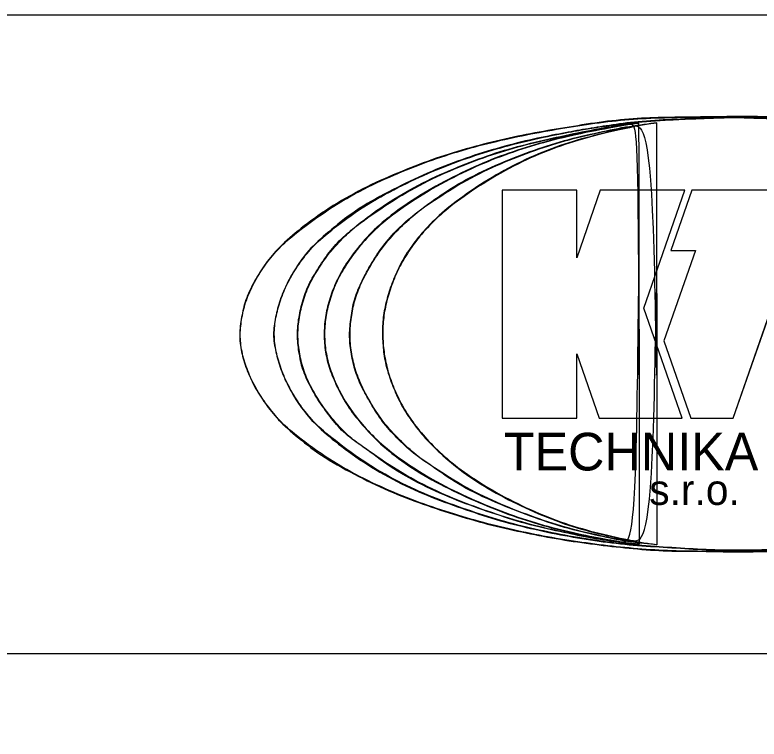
# Model space of a CAD drawing. Extents: x 25 to 46, y -90 to -60.3.
# Drawn here: x 37.705 to 40.036, y -77.068 to -74.8 of the extents above; entities that cross this region are included whole.
import ezdxf

# ---------------------------------------------------------------- set-up
doc = ezdxf.new("R2010")
doc.units = 0
doc.layers.add('_popis', color=7, linetype='Continuous')
doc.layers.add('Rozpiska_pole_6', color=7, linetype='Continuous')

msp = doc.modelspace()

# ---------------------------------------------------------------- linework, layer by layer
at = {"layer": '_popis'}
for p, q in [((39.2313, -75.3488), (39.2313, -76.0628)), ((39.465, -75.3488), (39.2313, -75.3488)), ((39.5386, -75.3488), (39.465, -75.5605)), ((39.465, -75.5605), (39.465, -75.3488)), ((39.8036, -75.3488), (39.5386, -75.3488)), ((39.675, -75.7182), (39.8036, -75.3488)), ((39.825, -75.3488), (39.7594, -75.5375)), ((40.2641, -75.3488), (39.825, -75.3488)), ((39.8369, -75.5375), (39.7381, -75.8213)), ((39.7594, -75.5375), (39.8369, -75.5375)), ((39.9551, -76.0628), (40.1379, -75.5375)), ((39.795, -76.0628), (39.675, -75.7182)), ((39.7381, -75.8213), (39.8222, -76.0628)), ((39.465, -76.0628), (39.465, -75.8616)), ((39.465, -75.8616), (39.535, -76.0628)), ((39.2313, -76.0628), (39.465, -76.0628)), ((39.535, -76.0628), (39.795, -76.0628)), ((39.8222, -76.0628), (39.9551, -76.0628))]:
    msp.add_line(p, q, dxfattribs=at)
for points in [[(39.2313, -75.3488), (39.2313, -76.0628), (39.465, -76.0628), (39.465, -75.8616), (39.535, -76.0628), (39.795, -76.0628), (39.675, -75.7182), (39.8036, -75.3488), (39.5386, -75.3488), (39.465, -75.5605), (39.465, -75.3488), (39.2313, -75.3488)], [(39.825, -75.3488), (39.7594, -75.5375), (39.8369, -75.5375), (39.7381, -75.8213), (39.8222, -76.0628), (39.9551, -76.0628), (40.1379, -75.5375), (40.1984, -75.5375), (40.2641, -75.3488), (39.825, -75.3488)]]:
    msp.add_lwpolyline(points, dxfattribs=at)
for points in [[(39.9639, -75.1182), (39.9235, -75.1188), (39.852, -75.1199), (39.7448, -75.1208), (39.642, -75.1242), (39.5347, -75.1357), (39.4277, -75.1537), (39.3201, -75.1713), (39.2128, -75.1946), (39.1051, -75.2223), (38.9975, -75.2573), (38.8906, -75.3005), (38.7817, -75.3493), (38.6736, -75.4136), (38.589, -75.4768), (38.5246, -75.5353), (38.4849, -75.5846), (38.452, -75.639), (38.4265, -75.6924), (38.4148, -75.7474), (38.4067, -75.8011), (38.4133, -75.8559), (38.4303, -75.9096), (38.4542, -75.9643), (38.4893, -76.0177), (38.5268, -76.0666), (38.5904, -76.1238), (38.6724, -76.1873), (38.7823, -76.2472), (38.8896, -76.2978), (38.9979, -76.3377), (39.1054, -76.3729), (39.2125, -76.4023), (39.3197, -76.4256), (39.427, -76.4454), (39.5348, -76.4603), (39.6419, -76.4721), (39.7493, -76.4805), (39.8565, -76.4792), (39.9639, -76.483), (40.0712, -76.4798), (40.1532, -76.4786), (40.1993, -76.4763), (40.2097, -76.4757)], [(39.9639, -75.1182), (39.8427, -75.1199), (39.7495, -75.1211), (39.6423, -75.1255), (39.5351, -75.1368), (39.4279, -75.1536), (39.3205, -75.1722), (39.2133, -75.1952), (39.1061, -75.2232), (38.9987, -75.2583), (38.8915, -75.3009), (38.7849, -75.3503), (38.6775, -75.4138), (38.5703, -75.4945), (38.5286, -75.5334), (38.4849, -75.5873), (38.4523, -75.6406), (38.4282, -75.6944), (38.4153, -75.7478), (38.4091, -75.8015), (38.4147, -75.8543), (38.431, -75.9085), (38.4551, -75.9623), (38.4888, -76.0156), (38.532, -76.0694), (38.5702, -76.1052), (38.6774, -76.1865), (38.7846, -76.2471), (38.8906, -76.2964), (38.9989, -76.3373), (39.1065, -76.3723), (39.2131, -76.4014), (39.3197, -76.425), (39.4275, -76.4446), (39.535, -76.4598), (39.6427, -76.4716), (39.7487, -76.4789), (39.8568, -76.4801), (39.9639, -76.4818), (40.0711, -76.4801), (40.1786, -76.4773), (40.2858, -76.4705), (40.3924, -76.4605), (40.4999, -76.4442), (40.6071, -76.4251), (40.7143, -76.401), (40.8218, -76.3713), (40.929, -76.336), (41.0362, -76.2945), (41.1428, -76.2446), (41.2508, -76.1813), (41.3585, -76.0978), (41.3905, -76.0692), (41.4326, -76.0159), (41.468, -75.9626), (41.4928, -75.9085), (41.5102, -75.8552), (41.5187, -75.8015), (41.5124, -75.748), (41.4939, -75.6942), (41.4698, -75.6394), (41.4378, -75.5872), (41.3924, -75.5334), (41.3593, -75.5009), (41.2509, -75.417), (41.1437, -75.3537), (41.0373, -75.3029), (40.9295, -75.2614), (40.8218, -75.2244), (40.7152, -75.1964), (40.6071, -75.1722), (40.4994, -75.1537), (40.3917, -75.1386), (40.2853, -75.125), (40.1784, -75.1211), (40.0713, -75.1192), (39.9639, -75.1182), (39.9639, -75.1182), (39.9639, -75.1182)], [(39.9639, -75.1211), (39.9997, -75.1226), (40.0713, -75.1255), (40.1787, -75.1265), (40.2858, -75.1383), (40.393, -75.1519), (40.5005, -75.1698), (40.6076, -75.1935), (40.7158, -75.2191), (40.8227, -75.2556), (40.9309, -75.2969), (41.0378, -75.3497), (41.1493, -75.4096), (41.2316, -75.4752), (41.2925, -75.5363), (41.331, -75.5848), (41.364, -75.639), (41.3885, -75.6928), (41.4013, -75.7476), (41.406, -75.8017), (41.4019, -75.8563), (41.3856, -75.9101), (41.3615, -75.9642), (41.3273, -76.0178), (41.2909, -76.0655), (41.2291, -76.1234), (41.1493, -76.1893), (41.0386, -76.2517), (40.9304, -76.3018), (40.8228, -76.3436), (40.715, -76.3773), (40.6078, -76.4072), (40.5001, -76.4295), (40.393, -76.4491), (40.2855, -76.4596), (40.1784, -76.4688), (40.0713, -76.4757), (39.9639, -76.4792), (39.8566, -76.4751), (39.7494, -76.4675), (39.6419, -76.4616), (39.5346, -76.4489), (39.4272, -76.4315), (39.3199, -76.4087), (39.2119, -76.3821), (39.1053, -76.3453), (38.9969, -76.3064), (38.8884, -76.2571), (38.7805, -76.1918), (38.696, -76.1276), (38.6313, -76.0686), (38.5928, -76.0182), (38.5608, -75.9637), (38.5367, -75.9099), (38.5218, -75.8558), (38.5123, -75.8015), (38.5206, -75.7471), (38.5345, -75.693), (38.5572, -75.6389), (38.589, -75.5849), (38.6276, -75.5322), (38.6946, -75.4726), (38.7792, -75.4054), (38.8901, -75.3461), (38.997, -75.2943), (39.1048, -75.2523), (39.2124, -75.218), (39.32, -75.1904), (39.4116, -75.1723), (39.4832, -75.1591), (39.5546, -75.1477), (39.6419, -75.1348), (39.7494, -75.1281), (39.8567, -75.1236), (39.9282, -75.122), (39.9639, -75.1211)], [(39.9639, -75.1211), (39.8567, -75.124), (39.7495, -75.1284), (39.6423, -75.1363), (39.5351, -75.1509), (39.4869, -75.1587), (39.428, -75.1694), (39.3205, -75.1913), (39.2133, -75.2188), (39.1059, -75.2532), (38.9988, -75.2952), (38.8914, -75.3463), (38.7848, -75.4063), (38.6775, -75.4883), (38.6298, -75.5333), (38.5888, -75.5872), (38.558, -75.6404), (38.5355, -75.6944), (38.5215, -75.7477), (38.5153, -75.8015), (38.5226, -75.8551), (38.5377, -75.9083), (38.5613, -75.9622), (38.5928, -76.0158), (38.6349, -76.0696), (38.6775, -76.11), (38.7847, -76.1919), (38.8914, -76.256), (38.9986, -76.3054), (39.1058, -76.3452), (39.2132, -76.3807), (39.3204, -76.4082), (39.4276, -76.4306), (39.535, -76.4482), (39.6422, -76.4605), (39.7494, -76.4678), (39.8567, -76.4745), (39.9639, -76.4779), (40.0711, -76.4751), (40.1786, -76.4684), (40.2852, -76.4594), (40.3924, -76.4476), (40.4999, -76.4291), (40.607, -76.4061), (40.7142, -76.3769), (40.8217, -76.3426), (40.9289, -76.3011), (41.0361, -76.2512), (41.1435, -76.1886), (41.2507, -76.1028), (41.285, -76.0695), (41.3277, -76.0156), (41.3608, -75.9624), (41.3849, -75.9085), (41.4, -75.8553), (41.4045, -75.802), (41.4, -75.7479), (41.3871, -75.6947), (41.3636, -75.6408), (41.331, -75.5872), (41.2883, -75.5333), (41.2507, -75.4952), (41.1436, -75.4105), (41.0362, -75.3496), (40.929, -75.298), (40.8218, -75.256), (40.7144, -75.2206), (40.6073, -75.1937), (40.5001, -75.1707), (40.3926, -75.1526), (40.2855, -75.1385), (40.1786, -75.1283), (40.0714, -75.1249), (39.9639, -75.1211), (39.9639, -75.1211), (39.9639, -75.1211)], [(40.2097, -76.4757), (40.235, -76.4743), (40.296, -76.4699), (40.3931, -76.4618), (40.5, -76.4443), (40.6076, -76.426), (40.715, -76.4017), (40.8225, -76.3721), (40.93, -76.3366), (41.0376, -76.2954), (41.1457, -76.2449), (41.256, -76.1823), (41.3346, -76.1179), (41.398, -76.0648), (41.4318, -76.0169), (41.4691, -75.965), (41.4932, -75.9098), (41.5113, -75.8562), (41.5216, -75.8018), (41.5143, -75.7463), (41.4938, -75.6932), (41.471, -75.6383), (41.4374, -75.5837), (41.3984, -75.5387), (41.3381, -75.4793), (41.2557, -75.4172), (41.1464, -75.3533), (41.0387, -75.3015), (40.9301, -75.2615), (40.8235, -75.2229), (40.7151, -75.1961), (40.6078, -75.1712), (40.4996, -75.1531), (40.3922, -75.1391), (40.2856, -75.1225), (40.1783, -75.1213), (40.0712, -75.119), (39.9997, -75.1184), (39.9639, -75.1182)], [(39.6602, -76.458), (39.6397, -76.4563), (39.5976, -76.4528), (39.5198, -76.4409), (39.4269, -76.4217), (39.3184, -76.3987), (39.2116, -76.3644), (39.1038, -76.3273), (38.9959, -76.2806), (38.8864, -76.2219), (38.8103, -76.1619), (38.7425, -76.1172), (38.7024, -76.072), (38.6615, -76.0175), (38.6297, -75.9637), (38.605, -75.9105), (38.5941, -75.8555), (38.5881, -75.8016), (38.5939, -75.7473), (38.6063, -75.6931), (38.6272, -75.6379), (38.6605, -75.5856), (38.6988, -75.5289), (38.7427, -75.4867), (38.8068, -75.4345), (38.8874, -75.3779), (38.9961, -75.3167), (39.1047, -75.2712), (39.2116, -75.2305), (39.3197, -75.2014), (39.4279, -75.1771), (39.5349, -75.1558), (39.6124, -75.142), (39.6542, -75.1395), (39.6598, -75.1392)], [(39.6602, -76.458), (39.5987, -76.4522), (39.5345, -76.4427), (39.4273, -76.4217), (39.3195, -76.397), (39.212, -76.3641), (39.1053, -76.3263), (38.9986, -76.2801), (38.891, -76.2205), (38.7832, -76.1443), (38.7543, -76.1238), (38.7017, -76.0697), (38.6611, -76.0148), (38.6301, -75.9622), (38.6069, -75.9092), (38.5948, -75.8548), (38.59, -75.8012), (38.5948, -75.7486), (38.6074, -75.694), (38.6284, -75.64), (38.66, -75.587), (38.6984, -75.5334), (38.753, -75.4787), (38.7825, -75.4546), (38.891, -75.3782), (38.9993, -75.3178), (39.1062, -75.2713), (39.2118, -75.2324), (39.3215, -75.2018), (39.4277, -75.1776), (39.5355, -75.1561), (39.643, -75.1403), (39.6598, -75.1392), (39.6602, -76.458), (39.6598, -75.1392)], [(39.6598, -75.1392), (39.6211, -75.145), (39.5434, -75.1566), (39.4299, -75.18), (39.3193, -75.2104), (39.2112, -75.2461), (39.1041, -75.2935), (38.9959, -75.3501), (38.9011, -75.412), (38.8266, -75.4743), (38.7771, -75.5313), (38.7382, -75.5846), (38.7093, -75.6388), (38.6886, -75.693), (38.6762, -75.7474), (38.6726, -75.8018), (38.6765, -75.8558), (38.6901, -75.9101), (38.7131, -75.9634), (38.7413, -76.0185), (38.7818, -76.0714), (38.8307, -76.127), (38.9025, -76.1891), (38.9959, -76.2499), (39.1046, -76.3045), (39.2124, -76.3503), (39.3194, -76.3886), (39.4271, -76.4174), (39.5243, -76.4371), (39.6021, -76.4501), (39.6439, -76.4558), (39.6602, -76.458)], [(39.6598, -75.1392), (39.5441, -75.1576), (39.4279, -75.1817), (39.3201, -75.2112), (39.2125, -75.2476), (39.1063, -75.2938), (38.9991, -75.3506), (38.8916, -75.4218), (38.8243, -75.4796), (38.7764, -75.5337), (38.7386, -75.5868), (38.7102, -75.6399), (38.6896, -75.6943), (38.6775, -75.7484), (38.6738, -75.8014), (38.678, -75.8554), (38.6912, -75.9085), (38.7133, -75.9621), (38.7422, -76.0162), (38.7811, -76.0693), (38.829, -76.1228), (38.8926, -76.1785), (38.9988, -76.2489), (39.1066, -76.3041), (39.2136, -76.3496), (39.3208, -76.3874), (39.4276, -76.4163), (39.5351, -76.4385), (39.6113, -76.4511), (39.6602, -76.458), (39.6598, -75.1392), (39.6602, -76.458)], [(39.7161, -76.4596), (39.6914, -76.4575), (39.6304, -76.4523), (39.5347, -76.4318), (39.4265, -76.4074), (39.3198, -76.3704), (39.2116, -76.3288), (39.1018, -76.2769), (39.021, -76.2196), (38.9493, -76.1723), (38.9019, -76.1253), (38.8532, -76.0728), (38.8201, -76.0165), (38.7893, -75.964), (38.7686, -75.9101), (38.7572, -75.8559), (38.7513, -75.8017), (38.7578, -75.7476), (38.7662, -75.6929), (38.7884, -75.6393), (38.817, -75.5858), (38.8518, -75.5308), (38.8972, -75.476), (38.9485, -75.4304), (39.0183, -75.3777), (39.1027, -75.3224), (39.2113, -75.2692), (39.3191, -75.2272), (39.4263, -75.1919), (39.5343, -75.1674), (39.6305, -75.1475), (39.6915, -75.1406), (39.7161, -75.1377)], [(39.7161, -76.4596), (39.6424, -76.452), (39.5346, -76.4316), (39.4284, -76.4058), (39.3206, -76.3701), (39.2131, -76.3279), (39.1064, -76.2754), (38.9989, -76.2052), (38.9585, -76.1768), (38.9001, -76.1227), (38.8538, -76.0696), (38.8196, -76.0157), (38.7902, -75.9621), (38.7697, -75.9085), (38.7581, -75.856), (38.7533, -75.8017), (38.7581, -75.7475), (38.7681, -75.6945), (38.7886, -75.6412), (38.8175, -75.5866), (38.8517, -75.5335), (38.8964, -75.4796), (38.9552, -75.426), (38.9994, -75.3924), (39.1063, -75.3233), (39.213, -75.2702), (39.3208, -75.2277), (39.4272, -75.1935), (39.5345, -75.1677), (39.6424, -75.1471), (39.7161, -75.1377), (39.7161, -76.4596), (39.7161, -75.1377)], [(39.7161, -75.1377), (39.6915, -75.1413), (39.6306, -75.1502), (39.5345, -75.1738), (39.426, -75.2027), (39.3179, -75.2449), (39.2101, -75.3004), (39.1156, -75.3622), (39.0382, -75.4217), (38.9841, -75.4775), (38.9415, -75.531), (38.9092, -75.5853), (38.8859, -75.6396), (38.8686, -75.6935), (38.8574, -75.7474), (38.8558, -75.8015), (38.8589, -75.8555), (38.8693, -75.9097), (38.8885, -75.9631), (38.9121, -76.0178), (38.946, -76.0711), (38.9886, -76.1254), (39.0426, -76.1786), (39.1162, -76.2399), (39.21, -76.2985), (39.3183, -76.352), (39.4258, -76.3958), (39.5342, -76.4259), (39.631, -76.446), (39.6914, -76.4557), (39.7161, -76.4596)], [(39.7161, -75.1377), (39.6424, -75.1494), (39.5353, -75.174), (39.4276, -75.2044), (39.3205, -75.2459), (39.2132, -75.3011), (39.1061, -75.3706), (39.0357, -75.4266), (38.9836, -75.4798), (38.9415, -75.5336), (38.9099, -75.5869), (38.8865, -75.6407), (38.8694, -75.6943), (38.8589, -75.7481), (38.8565, -75.8013), (38.86, -75.8551), (38.8706, -75.9089), (38.8887, -75.9621), (38.9128, -76.0157), (38.9461, -76.0695), (38.9877, -76.1221), (39.0416, -76.1762), (39.106, -76.2294), (39.213, -76.2978), (39.3203, -76.3513), (39.4274, -76.394), (39.5356, -76.425), (39.6423, -76.4473), (39.7161, -76.4596), (39.7161, -75.1377), (39.7161, -76.4596)]]:
    msp.add_open_spline(points, degree=3, dxfattribs=at)
at = {"layer": 'Rozpiska_pole_6'}
msp.add_line((27, -76.8), (44, -76.8), dxfattribs=at)
msp.add_lwpolyline([(27, -74.8), (44, -74.8), (44, -79.8), (27, -79.8)], close=True, dxfattribs=at)

# ---------------------------------------------------------------- texts
at = {"layer": '_popis'}
for s, height, p in [('TECHNIKA', 0.11795, (39.2362, -76.2268)), ('s.r.o.', 0.09543, (39.6919, -76.3347))]:
    msp.add_text(s, height=height, dxfattribs=at).set_placement(p)

doc.saveas('drawing.dxf')
